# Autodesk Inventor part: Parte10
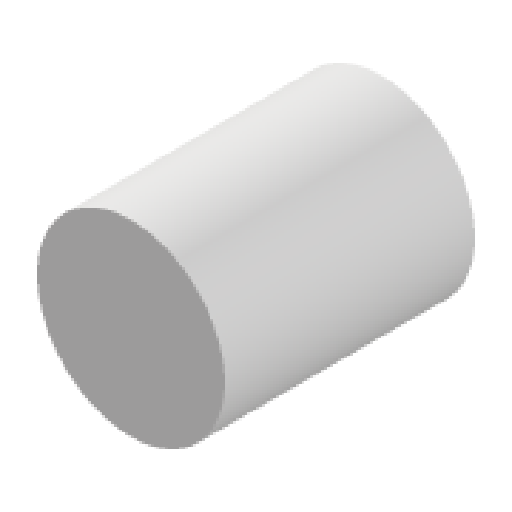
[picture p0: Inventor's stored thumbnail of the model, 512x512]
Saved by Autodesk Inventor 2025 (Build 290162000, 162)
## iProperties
Created: 2025-10
Part Number: Parte10
Material: Generico
Document SubType Name: Modeling
Designer: Ryzen5700u
Density: 1 g/cm^3
Appearance: Default
Author: Ryzen5700u
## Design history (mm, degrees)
sketch "Schizzo1"
  geometry: C1 r 15 at (0, 0); 1 further point
  constraints: 1 centre point, 1 coincident
  dimensions: "d0" = 30 diameter of C1
extrude "Estrusione1" new body sketch "Schizzo1" distance "d1" = 40; taper "d2" = 0 deg
node "Solido1"
